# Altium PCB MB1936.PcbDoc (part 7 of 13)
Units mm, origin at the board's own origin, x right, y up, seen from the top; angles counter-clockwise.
Board outline 172 x 137 mm, 6 copper layers (Top Layer, Signal Layer 1, Signal Layer 2, Signal Layer 3, Signal Layer 4, Bottom Layer), stack 1.549 mm thick; 859 components, 672 nets, 3477 pads, 2222 vias.
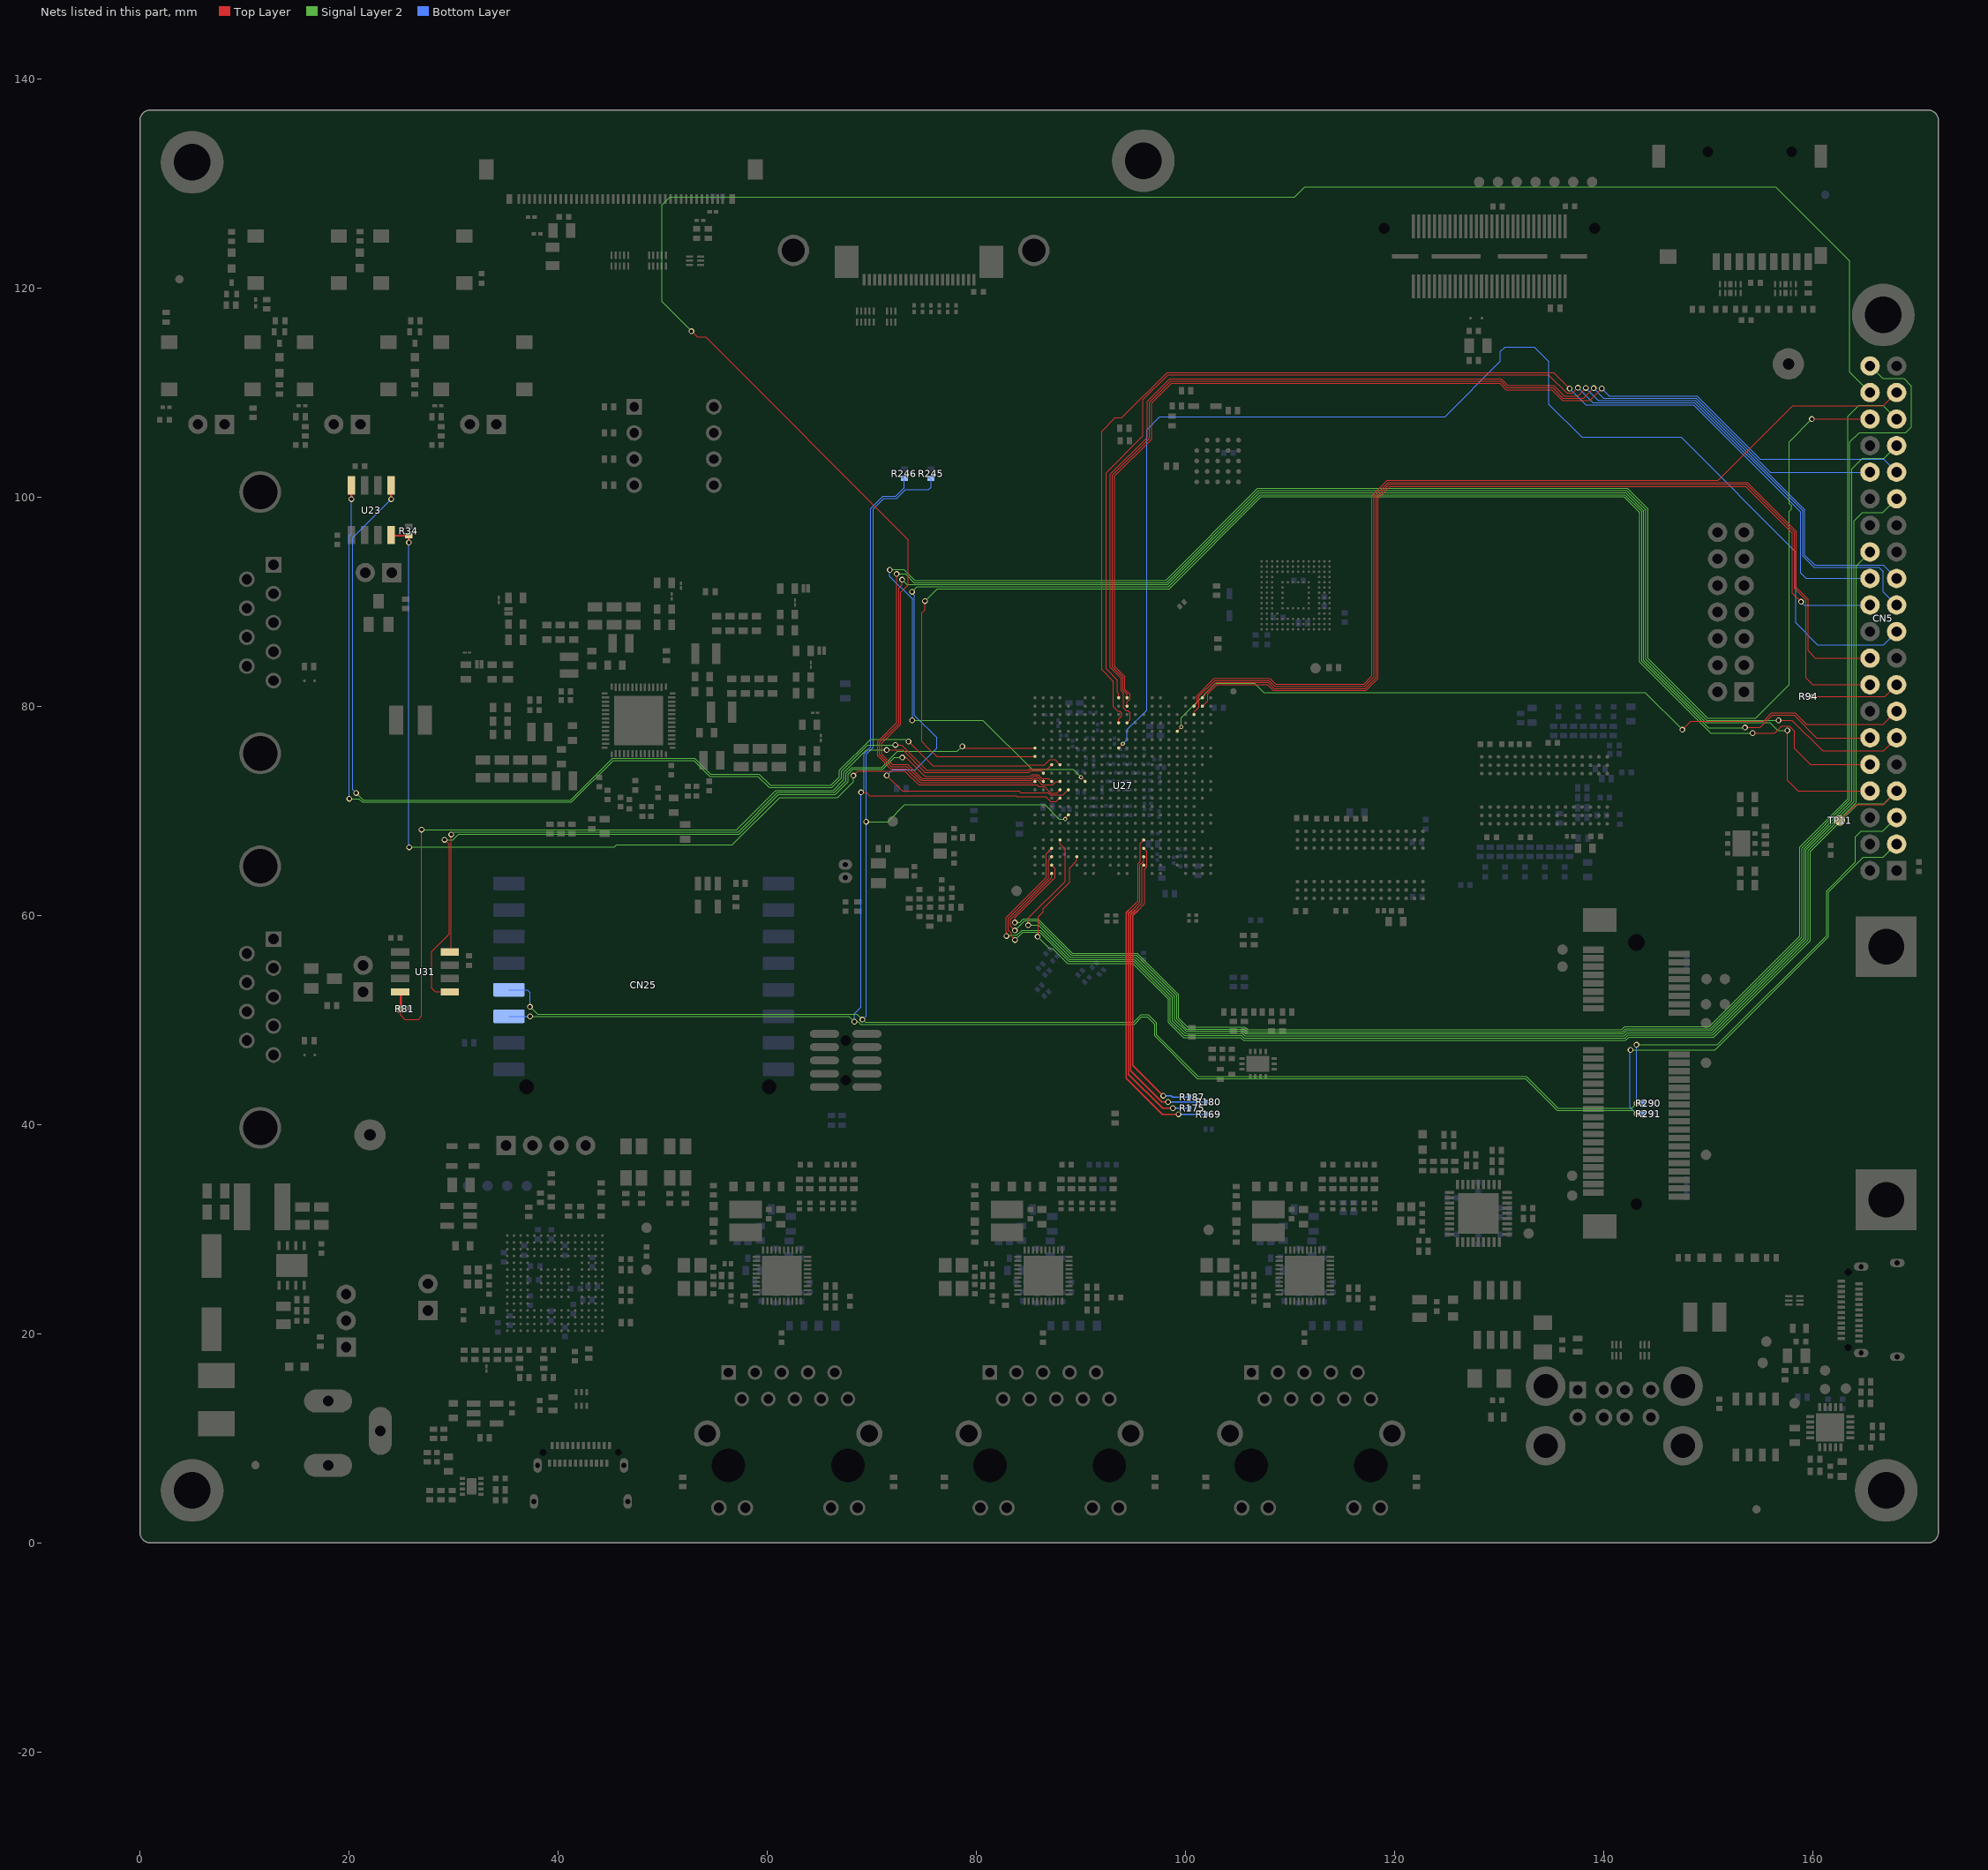
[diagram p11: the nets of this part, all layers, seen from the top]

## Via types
v1: diameter 0.55, hole 0.35, Top Layer to Bottom Layer, 1661 vias
v2: diameter 0.4, hole 0.2, Top Layer to Bottom Layer, tented both sides, 253 vias
v3: diameter 0.5, hole 0.2, Top Layer to Bottom Layer, 157 vias
v4: diameter 0.5, hole 0.25, Top Layer to Bottom Layer, 145 vias
v5: diameter 0.4, hole 0.2, Top Layer to Bottom Layer, 6 vias

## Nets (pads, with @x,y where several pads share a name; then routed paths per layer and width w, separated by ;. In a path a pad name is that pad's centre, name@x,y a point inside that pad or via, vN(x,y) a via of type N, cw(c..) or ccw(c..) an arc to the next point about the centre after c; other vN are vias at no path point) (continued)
ETH3.TXD0: R169.1 U27.V14 | length 32.4
  Top Layer w0.09: 94.547,60.475 95.455,61.383 95.455,64.913 95.675,65.133 95.675,66.875 U27.V14@96,67.2
  Top Layer w0.11: 94.547,60.475 94.335,60.263 94.335,44.44 97.789,40.986 v1(99.321,40.986)
  Bottom Layer w0.11: v1(99.321,40.986) 99.331,40.975 R169.1@101.9,40.975
ETH3.TXD1: R175.1 U27.Y14 | length 28.6
  Top Layer w0.09: 94.844,60.475 95.635,61.266 95.635,64.838 96,65.203 U27.Y14@96,65.6
  Top Layer w0.11: 94.844,60.475 94.545,60.176 94.545,44.805 97.797,41.553 v1(98.792,41.553)
  Bottom Layer w0.11: v1(98.792,41.553) 98.794,41.55 R175.1@100.35,41.55
ETH3.TXD2: R180.1 U27.AA14 | length 28.6
  Top Layer w0.09: 95.141,60.475 95.833,61.167 95.833,64.576 96,64.743 U27.AA14@96,64.8
  Top Layer w0.11: 95.141,60.475 94.755,60.089 94.755,45.145 97.753,42.147 v1(98.322,42.147)
  Bottom Layer w0.11: v1(98.322,42.147) 98.325,42.15 R180.1@101.9,42.15
ETH3.TXD3: R187.1 U27.W14 | length 28.1
  Top Layer w0.09: 95.438,60.475 96.081,61.118 96.081,64.406 96.295,64.62 96.295,66.105 U27.W14@96,66.4
  Top Layer w0.11: 95.438,60.475 94.965,60.002 94.965,45.66 v1(97.875,42.75)
  Bottom Layer w0.11: v1(97.875,42.75) 98.6,42.75 98.725,42.625 R187.1@100.35,42.625
EXP_GPIO2: CN5.3 CN25.11 R246.1 R291.2 U27.N4 | length 230.2
  Top Layer w0.09: 81.172,71.44 83.822,71.44 83.907,71.355 85.276,71.355 85.425,71.355 86.626,71.355 87.106,70.875 87.625,70.875 87.95,71.2 U27.N4@88,71.2
  Top Layer w0.1: v1(68.975,71.75) 69.465,71.75 69.775,71.44 81.172,71.44
  Signal Layer 2 w0.1: v1(37.31,50.335) 67.815,50.335 v1(68.325,49.825) ; v1@68.378,49.878 68.423,49.833 68.691,49.833 68.936,49.588 95.108,49.588 95.795,50.275 96.351,50.275 97.044,49.582 97.044,48.481 101.125,44.4 132.5,44.4 135.55,41.35 142.775,41.35 v1(143.125,41) ; v1(142.55,47.125) 150.65,47.125 161.5,57.975 161.5,62.225 164.825,65.55 166.735,65.55 CN5.3@167.995,66.81
  Bottom Layer w0.1: CN25.11@35.295,50.34 v1@37.305,50.34 ; v1(68.325,49.825) 68.325,50.575 68.975,51.225 v1(68.975,71.75) 69.25,72.025 69.25,75.458 69.9,76.108 69.9,98.908 71.057,100.065 72.29,100.065 73.109,100.884 R246.1@73.109,101.775 ; v1(142.55,47.125) 142.5,47.075 142.5,41.625 v1(143.125,41) R291.2@143.8,41
EXP_GPIO3: CN5.5 CN25.12 R245.1 R290.2 U27.R5 | length 236.1
  Top Layer w0.09: v2(88.496,69.205) 88.496,69.25 88.8,69.555 U27.R5@88.8,69.6
  Signal Layer 2 w0.1: v1(37.3,51.25) 38.015,50.535 68.59,50.535 v1(69.1,50.025) ; v1@69.145,50.025 69.382,49.788 95.026,49.788 95.752,50.514 96.421,50.514 97.244,49.692 97.244,48.564 101.208,44.6 132.583,44.6 135.608,41.575 142.675,41.575 v1(143.125,42.025) ; v1(69.45,68.95) 71.525,68.95 73.15,70.575 86.55,70.575 87.92,69.205 v2(88.496,69.205) ; v1(143.125,47.625) 150.867,47.625 161.3,58.058 161.3,62.308 164.075,65.083 164.075,67.5 164.625,68.05 166.695,68.05 CN5.5@167.995,69.35
  Bottom Layer w0.1: CN25.12@35.295,52.88 37.045,52.88 37.3,52.625 v1(37.3,51.25) ; v1(69.1,50.025) 69.45,50.375 v1(69.45,68.95) 69.45,75.375 70.125,76.05 70.125,83.151 70.132,83.158 70.132,98.857 71.14,99.865 72.373,99.865 73.208,100.7 75.428,100.7 75.649,100.921 R245.1@75.649,101.775 ; v1(143.125,47.625) v1(143.125,42.025) R290.2@143.8,42.025
EXP_GPIO4: CN5.7 TP11.1 U27.Y6 | length 118.2
  Top Layer w0.1: v1(85.85,57.95) 85.9,58 85.9,59.85 86.39,60.34 86.39,60.627 88.912,63.149 88.912,64.522 89.6,65.21 U27.Y6@89.6,65.6 ; TP11.1@162.575,69.075 164.1,70.6 166.705,70.6 CN5.7@167.995,71.89
  Signal Layer 2 w0.1: v1(85.85,57.95) 86.971,56.829 87.278,56.829 88.72,55.387 94.95,55.387 98.356,51.981 98.356,49.755 99.786,48.325 105.262,48.325 105.537,48.05 142.092,48.05 142.405,48.362 150.513,48.362 159.75,57.6 159.75,66.125 164.303,70.678 166.783,70.678 CN5.7@167.995,71.89
EXP_GPIO5: CN5.29 U27.W3 | length 143
  Top Layer w0.1: v1(82.875,58.031) 82.875,58.462 82.85,58.487 82.85,59.788 86.69,63.628 86.69,65.89 U27.W3@87.2,66.4
  Signal Layer 2 w0.1: v1(82.875,58.031) 82.924,58.08 83.845,58.08 84.34,58.575 86.127,58.575 88.915,55.787 95.116,55.787 98.756,52.147 98.756,49.921 99.951,48.725 105.427,48.725 105.677,48.475 141.951,48.475 142.239,48.762 150.347,48.762 159.35,57.766 159.35,66.291 163.925,70.866 163.925,97.725 164.725,98.525 166.69,98.525 CN5.29@167.995,99.83
EXP_GPIO6: CN5.31 U27.B12 | length 107.7
  Top Layer w0.09: 93.22,84.475 93.21,84.465 93.21,83.797 94.205,82.802 94.205,81.611 94.685,81.131 94.685,80.682 94.4,80.397 U27.B12@94.4,80
  Top Layer w0.1: 93.22,84.475 93.22,102.014 96.745,105.539 96.745,108.961 98.659,110.875 130.043,110.875 130.658,110.26 135.012,110.26 136.027,109.245 138.67,109.245 v1(139.8,110.375)
  Bottom Layer w0.1: v1(139.8,110.375) 140.52,109.655 148.905,109.655 154.935,103.625 166.74,103.625 CN5.31@167.995,102.37
EXP_GPIO7: CN5.26 U27.Y3 | length 135
  Top Layer w0.1: v1(83.687,57.639) 83.325,58.001 83.325,58.295 83.05,58.57 83.05,59.705 86.88,63.535 86.88,65.28 U27.Y3@87.2,65.6
  Signal Layer 2 w0.1: v1(83.687,57.639) 84.422,58.375 86.044,58.375 88.832,55.587 95.033,55.587 98.556,52.064 98.556,49.838 99.869,48.525 105.344,48.525 105.594,48.275 142.034,48.275 142.322,48.562 150.43,48.562 159.55,57.683 159.55,66.208 164.125,70.783 164.125,93.42 CN5.26@165.455,94.75
EXP_GPIO8: CN5.24 U27.D11 | length 116.3
  Top Layer w0.09: 91.98,84.475 91.98,83.479 93.11,82.349 93.11,79.945 93.505,79.55 93.688,79.55 93.91,79.328 93.91,79.06 93.6,78.75 U27.D11@93.6,78.4
  Top Layer w0.1: 91.98,84.475 91.98,106.297 93.263,107.58 93.907,107.58 98.232,111.905 135.195,111.905 v1(136.725,110.375)
  Bottom Layer w0.1: v1(136.725,110.375) 138.275,108.825 148.575,108.825 158.825,98.575 158.825,92.725 159.34,92.21 CN5.24@165.455,92.21
EXP_GPIO9: CN5.21 U27.A11 | length 116.7
  Top Layer w0.09: 92.4,84.475 92.4,83.568 93.485,82.483 93.485,81.313 93.6,81.198 U27.A11@93.6,80.8
  Top Layer w0.1: 92.4,84.475 92.4,102.325 95.925,105.85 95.925,109.301 98.319,111.695 134.7,111.695 136.45,109.945 137.02,109.945 v1(137.525,110.45)
  Bottom Layer w0.1: v1(137.525,110.45) 138.94,109.035 148.662,109.035 159.025,98.672 159.025,94.35 160.075,93.3 166.3,93.3 166.723,92.877 166.723,90.942 CN5.21@167.995,89.67
EXP_GPIO10: CN5.19 U27.G11 | length 125.8
  Top Layer w0.09: U27.G11@93.6,76 v2@94,76.4
  Bottom Layer w0.1: v2(94,76.4) 94.4,76.8 94.4,77.75 96.286,79.635 96.286,106.426 97.529,107.67 124.804,107.67 130.115,112.98 130.115,113.924 130.541,114.35 133.35,114.35 134.75,112.95 134.75,108.867 137.892,105.725 147.375,105.725 158.363,94.737 158.363,87.962 160.45,85.875 166.74,85.875 CN5.19@167.995,87.13
EXP_GPIO11: CN5.23 U27.D12 | length 116.8
  Top Layer w0.09: 92.81,84.475 92.8,84.465 92.8,83.698 93.845,82.653 93.845,81.462 94.065,81.242 94.065,79.84 94.33,79.575 94.485,79.575 94.71,79.35 94.71,78.71 U27.D12@94.4,78.4
  Top Layer w0.1: 92.81,84.475 92.81,102.169 96.335,105.694 96.335,109.131 98.489,111.285 130.199,111.285 130.824,110.66 135.192,110.66 136.197,109.655 137.505,109.655 v1(138.275,110.425)
  Bottom Layer w0.1: v1(138.275,110.425) 139.455,109.245 148.749,109.245 159.225,98.769 159.225,94.433 160.158,93.5 166.705,93.5 CN5.23@167.995,92.21
EXP_GPIO12: CN5.32 U27.A12 | length 104.4
  Top Layer w0.09: 93.01,84.475 93.005,84.47 93.005,83.747 94.025,82.727 94.025,81.537 94.4,81.162 U27.A12@94.4,80.8
  Top Layer w0.1: 93.01,84.475 93.015,84.48 93.015,84.49 93.015,102.091 96.54,105.616 96.54,109.046 98.579,111.085 130.116,111.085 130.741,110.46 135.095,110.46 136.105,109.45 138.075,109.45 138.75,110.125 v1(139.025,110.4)
  Bottom Layer w0.1: v1(139.025,110.4) 139.97,109.455 148.822,109.455 155.907,102.37 CN5.32@165.455,102.37
EXP_GPIO13: CN5.33 U27.V4 | length 145.4
  Top Layer w0.1: v1(84.95,59.05) 84.95,59.725 88.49,63.265 88.49,66.32 88,66.81 U27.V4@88,67.2
  Signal Layer 2 w0.1: v1(84.95,59.05) 85.935,59.05 88.998,55.987 95.199,55.987 98.956,52.23 98.956,50.003 100.034,48.925 105.51,48.925 105.76,48.675 141.869,48.675 142.156,48.962 150.264,48.962 159.15,57.849 159.15,66.374 163.725,70.949 163.725,102.7 164.725,103.7 166.785,103.7 CN5.33@167.995,104.91
EXP_GPIO14: CN5.8 U27.L4 | length 155.8
  Top Layer w0.09: 85.748,73.055 85.885,72.918 85.885,72.898 86.278,72.505 87.308,72.505 87.603,72.8 U27.L4@88,72.8
  Top Layer w0.1: v1(72.894,92.094) 72.894,91.611 72.575,91.292 72.575,78.358 70.75,76.533 70.75,75.333 71.877,74.206 73.361,74.206 74.682,72.885 85.268,72.885 85.473,73.09 85.713,73.09 85.748,73.055 ; v1(157.55,77.675) 157.55,72.925 158.585,71.89 CN5.8@165.455,71.89
  Signal Layer 2 w0.1: v1(72.894,92.094) 73.363,91.625 98.266,91.625 107.066,100.425 142.098,100.425 143.825,98.698 143.825,84.384 149.769,78.44 155.86,78.44 156.625,77.675 v1(157.55,77.675)
EXP_GPIO15: CN5.10 U27.H1 | length 140
  Top Layer w0.1: v1(75.075,90.05) 75.075,89.2 74.8,88.925 74.8,76.599 75.35,76.049 76.199,75.2 84.614,75.2 U27.H1@85.6,75.2 ; v1(154.225,77.425) 156.325,77.425 157,78.1 157.726,78.1 158.25,77.576 158.25,75.925 159.745,74.43 CN5.10@165.455,74.43
  Signal Layer 2 w0.1: v1(75.075,90.05) 76.25,91.225 98.431,91.225 107.231,100.025 141.91,100.025 143.425,98.51 143.425,84.218 150.218,77.425 v1(154.225,77.425)
EXP_GPIO16: CN5.36 U27.L7 | length 175.2
  Top Layer w0.1: v2(90,73.2) U27.L7@90.4,72.8 ; v1(159.9,107.45) CN5.36@165.455,107.45
  Signal Layer 2 w0.1: v1(71.721,93.031) 71.752,93.062 73.063,93.062 74.1,92.025 98.1,92.025 106.9,100.825 142.264,100.825 144.225,98.864 144.225,84.55 149.935,78.84 154.525,78.84 157.732,82.047 157.732,98.631 157.925,98.824 157.925,99.176 157.732,99.369 157.732,105.282 v1(159.9,107.45) ; v1(73.85,78.65) 80.614,78.65 85.324,73.94 89.259,73.94 v2(90,73.2)
  Bottom Layer w0.1: v1(71.721,93.031) 71.721,92.413 73.875,90.259 73.875,78.675 v1(73.85,78.65)
EXP_GPIO17: CN5.11 U27.L1 | length 153.1
  Top Layer w0.1: v1(72.369,92.637) 72.375,92.631 72.375,78.441 70.55,76.616 70.55,75.25 71.794,74.006 73.278,74.006 74.599,72.685 85.431,72.685 85.546,72.8 U27.L1@85.6,72.8 ; v1(156.7,78.65) 158,78.65 160.925,75.725 166.75,75.725 CN5.11@167.995,76.97
  Signal Layer 2 w0.1: v1(72.369,92.637) 73.205,92.637 74.017,91.825 98.183,91.825 106.983,100.625 142.181,100.625 144.025,98.781 144.025,84.467 149.852,78.64 156.69,78.64 v1(156.7,78.65)
EXP_GPIO18: CN5.12 U27.M5 | length 154.6
  Top Layer w0.09: 81.172,71.875 84.075,71.875 84.235,71.715 86.827,71.715 87.047,71.495 88.295,71.495 U27.M5@88.8,72
  Top Layer w0.1: v1(71.421,73.375) 72.921,71.875 81.172,71.875 ; v1(153.5,77.95) 154.925,77.95 156.125,79.15 158.175,79.15 160.355,76.97 CN5.12@165.455,76.97
  Signal Layer 2 w0.1: v1(73.839,90.938) 74.326,91.425 98.349,91.425 107.149,100.225 141.993,100.225 143.625,98.593 143.625,84.301 150.001,77.925 153.475,77.925 v1(153.5,77.95)
  Bottom Layer w0.1: v1(71.421,73.375) 71.983,73.937 74.146,73.937 76.2,75.991 76.2,77 74.075,79.125 74.075,90.581 73.839,90.816 v1(73.839,90.938)
EXP_GPIO19: CN5.35 U27.AA3 | length 149.1
  Top Layer w0.1: v1(83.675,59.3) 83.675,59.765 87.52,63.61 87.52,64.48 U27.AA3@87.2,64.8
  Signal Layer 2 w0.1: v1(83.675,59.3) 84.129,59.3 84.504,59.675 85.876,59.675 89.164,56.387 95.365,56.387 99.356,52.396 99.356,50.169 100.2,49.325 105.676,49.325 105.926,49.075 141.703,49.075 141.99,49.362 150.098,49.362 158.75,58.014 158.75,66.539 163.325,71.114 163.325,107.725 164.378,108.778 166.667,108.778 CN5.35@167.995,107.45
EXP_GPIO20: CN5.38 U27.L2 | length 211.1
  Top Layer w0.1: v1(52.75,115.85) 53.3,115.3 54.092,115.3 73.478,95.914 73.478,91.601 72.775,90.897 72.775,78.275 70.95,76.45 70.95,75.416 71.96,74.406 73.444,74.406 74.765,73.085 85.199,73.085 85.394,73.28 85.792,73.28 86.162,72.91 86.236,72.91 86.346,72.8 U27.L2@86.4,72.8
  Signal Layer 2 w0.1: v1(52.75,115.85) 49.925,118.675 49.925,120.624 49.925,120.976 49.925,127.925 50.7,128.7 110.45,128.7 111.394,129.644 156.431,129.644 163.513,122.562 163.513,111.932 CN5.38@165.455,109.99
EXP_GPIO21: CN5.40 U27.AB3 | length 156.8
  Top Layer w0.1: v1(83.676,58.548) 83.25,58.974 83.25,59.623 87.2,63.573 U27.AB3@87.2,64
  Signal Layer 2 w0.1: v1(83.676,58.548) 84.602,59.475 85.793,59.475 89.081,56.187 95.282,56.187 99.156,52.313 99.156,50.086 100.117,49.125 105.593,49.125 105.843,48.875 141.786,48.875 142.073,49.162 150.181,49.162 158.95,57.931 158.95,66.456 163.525,71.031 163.525,105.259 164.429,106.162 168.887,106.162 169.425,106.7 169.425,110.6 168.7,111.325 166.66,111.325 CN5.40@165.455,112.53
EXP_GPIO22: CN5.15 R94.2 | length 8.6
  Top Layer w0.1: R94.2@159.85,80.9 R94.2@159.875,80.925 166.87,80.925 CN5.15@167.995,82.05
EXP_GPIO23: CN5.16 U27.A21 | length 98.4
  Top Layer w0.1: U27.A21@101.6,80.8 101.92,81.12 101.92,81.239 102.934,82.253 107.913,82.253 108.466,81.7 117.203,81.7 118.225,82.722 118.225,99.966 119.459,101.2 153.654,101.2 158.225,96.629 158.225,91.242 159.325,90.142 159.325,82.675 159.95,82.05 CN5.16@165.455,82.05
EXP_GPIO24: CN5.18 U27.C20 | length 98.1
  Top Layer w0.1: U27.C20@100.8,79.2 100.8,79.425 101.29,79.915 101.29,80.945 102.798,82.453 107.996,82.453 108.549,81.9 117.12,81.9 118.025,82.805 118.025,100.049 119.376,101.4 153.737,101.4 158.425,96.712 158.425,91.325 159.525,90.225 159.525,85.3 160.235,84.59 CN5.18@165.455,84.59
EXP_GPIO25: CN5.22 U27.B21 | length 91.6
  Top Layer w0.1: U27.B21@101.6,80 102.11,80.51 102.11,81.16 103.003,82.053 107.83,82.053 108.383,81.5 117.286,81.5 118.425,82.639 118.425,99.883 119.542,101 153.571,101 158.025,96.546 158.025,90.8 v1(158.85,89.975)
  Bottom Layer w0.1: v1(158.85,89.975) 159.155,89.67 CN5.22@165.455,89.67
EXP_GPIO26: CN5.37 U27.B20 | length 90.6
  Top Layer w0.1: U27.B20@100.8,80 101.1,80.3 101.1,81.023 102.73,82.653 108.078,82.653 108.631,82.1 117.037,82.1 117.825,82.888 117.825,100.131 119.294,101.6 150.925,101.6 158.05,108.725 166.73,108.725 CN5.37@167.995,109.99
EXP_GPIO27: CN5.13 U27.E18 | length 74.7
  Top Layer w0.09: U27.E18@99.2,77.6 v2@99.6,78
  Top Layer w0.1: v1(147.5,77.75) 148.325,78.575 155.267,78.575 156.042,79.35 158.258,79.35 159.358,78.25 166.735,78.25 CN5.13@167.995,79.51
  Signal Layer 2 w0.1: v2(99.6,78) 99.6,78.9 102.9,82.2 106.575,82.2 107.475,81.3 143.95,81.3 v1(147.5,77.75)
FDCAN1.RX: U23.4 U27.J3 | length 103.4
  Top Layer w0.09: 86.955,74.155 U27.J3@87.2,74.4
  Top Layer w0.1: v1(72.25,76.3) 72.825,76.3 75.24,73.885 84.953,73.885 85.088,74.02 86.82,74.02 86.955,74.155
  Top Layer w0.2: v1(20.224,99.796) U23.4@20.224,101.111 U23.4@20.224,101.121
  Signal Layer 2 w0.1: v1(20.025,71.15) 20.942,71.15 21.267,70.825 41.275,70.825 45.275,74.825 52.975,74.825 54.5,73.3 59.1,73.3 60.175,72.225 66.183,72.225 67.1,73.142 67.1,73.8 69.6,76.3 71.475,76.3 v1(72.25,76.3)
  Bottom Layer w0.1: v1(20.025,71.15) 20.025,96.3 20.224,96.499 v1(20.224,99.796)
FDCAN1.STBY: R34.1 U23.8 U27.M4 | length 98.2
  Top Layer w0.09: 81.172,72.485 85.787,72.485 85.977,72.295 86.522,72.295 86.905,71.912 86.905,71.892 87.122,71.675 87.675,71.675 U27.M4@88,72
  Top Layer w0.1: v1(68.225,73.35) 68.681,73.806 73.144,73.806 74.465,72.485 81.172,72.485
  Top Layer w0.2: U23.8@24.034,96.361 24.089,96.306 R34.1@25.721,96.306 ; v1(25.721,95.641) R34.1@25.721,96.306 ; R34.1@25.721,96.316 R34.1@25.721,96.306
  Signal Layer 2 w0.1: v1(25.75,66.5) 25.775,66.525 45.375,66.525 45.6,66.75 56.65,66.75 61.175,71.275 66.725,71.275 68.225,72.775 v1(68.225,73.35)
  Bottom Layer w0.1: v1(25.721,95.641) 25.721,66.529 v1(25.75,66.5)
FDCAN1.TX: U23.1 U27.J4 | length 105.1
  Top Layer w0.09: 81.172,74.285 84.836,74.285 84.936,74.385 86.527,74.385 87.027,74.885 87.515,74.885 U27.J4@88,74.4
  Top Layer w0.1: v1(73.5,76.625) 75.84,74.285 81.172,74.285
  Top Layer w0.2: v1(24.034,99.796) U23.1@24.034,101.111 U23.1@24.034,101.121
  Signal Layer 2 w0.1: v1(20.675,71.7) 21.35,71.025 41.192,71.025 45.192,75.025 53.058,75.025 54.583,73.5 59.233,73.5 60.308,72.425 66.1,72.425 66.9,73.225 66.9,73.883 69.867,76.85 71.425,76.85 73.216,76.85 73.441,76.625 v1(73.5,76.625)
  Bottom Layer w0.1: v1(20.675,71.7) 20.35,72.025 20.35,96.112 v1(24.034,99.796)
FDCAN3.RX: U27.G1 U31.4 | length 71.1
  Top Layer w0.1: U31.4@29.64,56.49 29.782,56.632 29.782,67.718 v1(29.775,67.725) ; v1(78.65,76.15) 78.772,76.15 78.922,76 U27.G1@85.6,76
  Signal Layer 2 w0.1: v1(29.775,67.725) 30.025,67.975 57.225,67.975 61,71.75 66.425,71.75 67.525,72.85 67.525,73.583 68.092,74.15 70.925,74.15 72.45,75.675 78.175,75.675 v1(78.65,76.15)
FDCAN3.STBY: R81.1 U27.K2 U31.8 | length 86.4
  Top Layer w0.09: 81.172,73.685 85.014,73.685 85.164,73.835 86.165,73.835 U27.K2@86.4,73.6
  Top Layer w0.1: R81.1@24.89,51.048 24.89,50.485 25.325,50.05 26.625,50.05 26.938,50.363 v1(26.938,68.187) ; U31.8@24.89,52.68 U31.8@24.945,52.68 ; v1(71.425,75.8) 72.975,75.8 75.09,73.685 81.172,73.685
  Top Layer w0.2: R81.1@24.945,51.103 U31.8@24.945,52.68
  Signal Layer 2 w0.1: v1(26.938,68.187) 26.95,68.175 57.05,68.175 60.825,71.95 66.3,71.95 67.325,72.975 67.325,73.666 69.459,75.8 v1(71.425,75.8)
FDCAN3.TX: U27.L3 U31.1 | length 79.8
  Top Layer w0.09: 85.596,73.47 85.601,73.465 85.877,73.465 86.247,73.095 86.905,73.095 U27.L3@87.2,72.8
  Top Layer w0.1: v1(29.125,67.225) 29.582,66.768 29.582,58.207 27.89,56.515 27.89,53.04 28.25,52.68 U31.1@29.64,52.68 ; v1(72.913,75.089) 72.915,75.087 73.28,75.087 75.081,73.285 85.13,73.285 85.315,73.47 85.596,73.47
  Signal Layer 2 w0.1: v1(29.125,67.225) 29.95,67.225 30.5,67.775 57.308,67.775 61.083,71.55 66.508,71.55 67.725,72.767 67.725,73.5 68.175,73.95 71.008,73.95 72.147,75.089 v1(72.913,75.089)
